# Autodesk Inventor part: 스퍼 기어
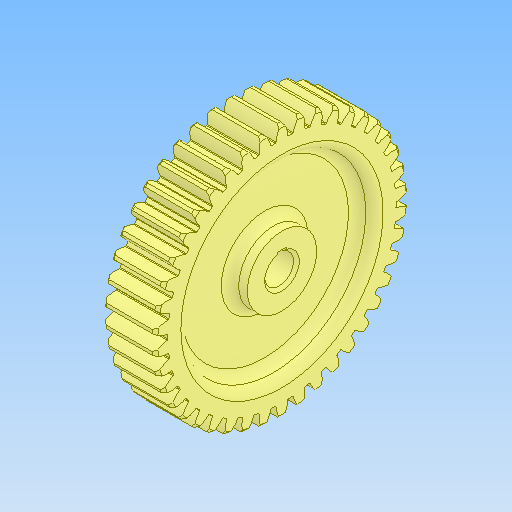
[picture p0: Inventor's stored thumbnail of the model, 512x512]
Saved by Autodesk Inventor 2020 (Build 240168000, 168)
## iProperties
Created: 2024-09
Part Number: 스퍼 기어
Material: 강철, 탄소
Document SubType Name: Modeling
Designer: oem
Density: 7.85 g/cm^3
Appearance: 기본값
Author: jhkim
Sending System: Autodesk Inventor 2025
Preprocessor: ST-DEVELOPER v20
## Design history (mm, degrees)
feature "솔리드1"
node "솔리드2"
